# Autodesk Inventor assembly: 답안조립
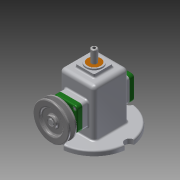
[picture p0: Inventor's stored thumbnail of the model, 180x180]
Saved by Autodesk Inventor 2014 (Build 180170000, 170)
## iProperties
Created: 2018-07
Part Number: 답안조립
Document SubType Name: Assembly
Designer: kh
Author: kh
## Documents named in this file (16)
- C:\Users\kh\Desktop\480707v1024\답안조립.iam
- C:\Users\kh\Desktop\480707v1024\답안본체.ipt
- C:\Users\kh\Desktop\480707v1024\뒤커버.ipt
- C:\Users\kh\Desktop\480707v1024\볼트 M4.ipt
- C:\Users\kh\Desktop\480707v1024\앞커버.ipt
- C:\Users\kh\Desktop\480707v1024\부시.ipt
- C:\Users\kh\Desktop\480707v1024\슬라이드.ipt
- C:\Users\kh\Desktop\480707v1024\오일 실 12 25 7.ipt
- C:\Users\kh\Desktop\480707v1024\편심축.ipt
- C:\Users\kh\Desktop\480707v1024\베어링 12x32x10.ipt
- C:\Users\kh\Desktop\480707v1024\키 4x4x10.ipt
- C:\Users\kh\Desktop\480707v1024\V벨트풀리.ipt
- C:\Users\kh\Desktop\480707v1024\멈춤나사 M3x8.ipt
- C:\Users\kh\Desktop\480707v1024\링크.ipt
- C:\Users\kh\Desktop\480707v1024\핀 5x18.ipt
- C:\Users\kh\Desktop\480707v1024\고정핀 1.2x8.ipt
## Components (3 placed, 3 different names)
1. V벨트풀리:1 — Insert:17, Mate:4
2. 핀 5x18:1 — Mate:7, Mate:8, Insert:20
3. 고정핀 1.2x8:1 — Mate:7, Mate:8
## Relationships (5: Mate 3, Insert 2)
- Insert:17: V벨트풀리:1
- Mate:4: V벨트풀리:1
- Mate:7: 핀 5x18:1 ↔ 고정핀 1.2x8:1
- Mate:8: 핀 5x18:1 ↔ 고정핀 1.2x8:1
- Insert:20: 핀 5x18:1
